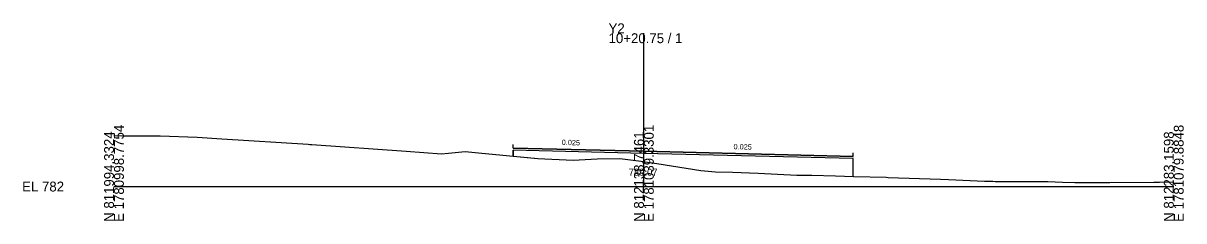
# Model space of a CAD drawing. Extents: x -26 to 303, y -10 to 3096.
# Drawn here: x -25.7 to 302.8, y 490.3 to 546.2 of the extents above; entities that cross this region are included whole.
import ezdxf

# ---------------------------------------------------------------- set-up
doc = ezdxf.new("R2010")
doc.units = 0
for name, color, linetype in [('Exist Cross Section Cell', 7, 'Continuous'), ('Exist XS Center Line Elevation Label', 7, 'Continuous'), ('Exist XS Ground Line', 7, 'Continuous'), ('Prop XS Dump Level', 7, 'Continuous'), ('Prop XS Earthwork Shape', 7, 'Continuous'), ('Prop XS EOT Tick Mark', 7, 'Continuous'), ('Prop XS Finish Grade Pavement', 7, 'Continuous'), ('Prop XS SE Text', 7, 'Continuous'), ('Prop XS Subgrade Earthwork', 7, 'Continuous')]:
    doc.layers.add(name, color=color, linetype=linetype)

msp = doc.modelspace()

# ---------------------------------------------------------------- linework, layer by layer
at = {"layer": 'Exist Cross Section Cell'}
for p, q in [((150, 500), (150, 543.39)), ((0, 500), (150, 500)), ((150, 500), (300, 500))]:
    msp.add_line(p, q, dxfattribs=at)
at = {"layer": 'Exist XS Ground Line'}
for p, q in [((0, 514.46), (2.59, 514.4)), ((2.59, 514.4), (12.4, 514.37)), ((12.4, 514.37), (13.04, 514.35)), ((13.04, 514.35), (23.53, 513.93)), ((23.53, 513.93), (30.52, 513.52)), ((30.52, 513.52), (54.98, 511.98)), ((54.98, 511.98), (55.44, 511.94)), ((55.44, 511.94), (56.02, 511.9)), ((56.02, 511.9), (82.76, 509.99)), ((82.76, 509.99), (92.72, 509.3)), ((92.72, 509.3), (94.66, 509.42)), ((94.66, 509.42), (99.41, 509.9)), ((99.41, 509.9), (103.15, 509.54)), ((103.15, 509.54), (119.96, 507.94)), ((119.96, 507.94), (129.98, 507.51)), ((129.98, 507.51), (136.82, 507.88)), ((136.82, 507.88), (143.24, 507.97)), ((143.24, 507.97), (150, 507.07)), ((150, 507.07), (150.4, 507.01)), ((150.4, 507.01), (153.63, 506.51)), ((153.63, 506.51), (166.08, 504.52)), ((166.08, 504.52), (170.29, 504.21)), ((170.29, 504.21), (175.08, 504.08)), ((175.08, 504.08), (182.34, 503.78)), ((182.34, 503.78), (193.29, 503.24)), ((193.29, 503.24), (197.54, 503.19)), ((197.54, 503.19), (204.24, 503.07)), ((204.24, 503.07), (209.47, 502.88)), ((209.47, 502.88), (218.61, 502.61)), ((218.61, 502.61), (219.19, 502.59)), ((219.19, 502.59), (233.94, 502.06)), ((233.94, 502.06), (236.21, 502.02)), ((236.21, 502.02), (246.38, 501.56)), ((246.38, 501.56), (248.81, 501.48)), ((248.81, 501.48), (249.48, 501.45)), ((249.48, 501.45), (250.48, 501.42)), ((250.48, 501.42), (252.22, 501.42)), ((252.22, 501.42), (260.12, 501.39)), ((260.12, 501.39), (263.86, 501.41)), ((263.86, 501.41), (264.39, 501.41)), ((264.39, 501.41), (268.46, 501.25)), ((268.46, 501.25), (271.99, 501.18)), ((271.99, 501.18), (281.92, 501.1)), ((281.92, 501.1), (294.37, 501.23)), ((294.37, 501.23), (295.92, 501.24)), ((295.92, 501.24), (300, 501.32))]:
    msp.add_line(p, q, dxfattribs=at)
at = {"layer": 'Prop XS Dump Level'}
for p, q in [((150, 509.98), (112.99, 510.9)), ((209.23, 508.51), (150, 509.98))]:
    msp.add_line(p, q, dxfattribs=at)
at = {"layer": 'Prop XS Earthwork Shape'}
msp.add_lwpolyline([(112.99, 508.61), (119.96, 507.94), (129.98, 507.51), (136.82, 507.88), (143.24, 507.97), (150, 507.07), (150.4, 507.01), (153.63, 506.51), (166.08, 504.52), (170.29, 504.21), (175.08, 504.08), (182.34, 503.78), (193.29, 503.24), (197.54, 503.19), (204.24, 503.07), (209.23, 502.89), (209.23, 507.92), (149.99, 509.4), (112.99, 510.32)], close=True, dxfattribs=at)
at = {"layer": 'Prop XS EOT Tick Mark'}
for p, q in [((112.99, 510.9), (112.99, 511.9)), ((209.23, 508.51), (209.23, 509.51))]:
    msp.add_line(p, q, dxfattribs=at)
at = {"layer": 'Prop XS Finish Grade Pavement'}
for p, q in [((112.99, 510.9), (150, 509.98)), ((150, 509.98), (209.23, 508.51))]:
    msp.add_line(p, q, dxfattribs=at)
at = {"layer": 'Prop XS Subgrade Earthwork'}
for p, q in [((112.99, 508.61), (112.99, 510.32)), ((149.99, 509.4), (112.99, 510.32)), ((209.23, 507.92), (149.99, 509.4)), ((209.23, 502.89), (209.23, 507.92))]:
    msp.add_line(p, q, dxfattribs=at)

# ---------------------------------------------------------------- texts
at = {"layer": 'Exist Cross Section Cell'}
for s, p in [('Y2', (140, 543.39)), ('10+20.75 / 1', (140, 540.59)), ('EL 782', (-26, 498.6))]:
    msp.add_text(s, height=2.8, dxfattribs=at).set_placement(p)
for s, p in [('E 1780998.7754', (2.8, 490)), ('E 1781039.3301', (152.8, 490)), ('E 1781079.8848', (302.8, 490)), ('N 811994.3324', (0, 490)), ('N 812138.7461', (150, 490)), ('N 812283.1598', (300, 490))]:
    msp.add_text(s, height=2.8, rotation=90, dxfattribs=at).set_placement(p)
at = {"layer": 'Exist XS Center Line Elevation Label'}
msp.add_text('789.07', height=2, dxfattribs=at).set_placement((145.7, 503.07))
at = {"layer": 'Prop XS SE Text'}
for p in [(126.73, 511.78), (175.36, 510.57)]:
    msp.add_text('0.025', height=1.5, rotation=358.5736, dxfattribs=at).set_placement(p)

doc.saveas('drawing.dxf')
